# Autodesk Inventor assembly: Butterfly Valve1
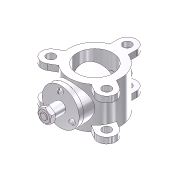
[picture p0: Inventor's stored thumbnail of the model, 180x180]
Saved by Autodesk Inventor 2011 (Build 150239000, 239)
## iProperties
Shininess: 64.0
Length Units: 11269
Angle Units: 11279
Time Units: 11290
Mass Units: 11283
Length Display Precision: 3
Angle Display Precision: 2
Created: 2002-02
Part Number: Butterfly Valve1
Document SubType Name: Assembly
Designer: ***
Density: 0.0
Volumn: 0.0
Area: 0.0
PropertySet Name: Model Information
Control State: 0
Master: False
Checked Out: False
Author: ***
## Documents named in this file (8)
- C:\Inventor_2011\c10_inv_2010_05042010\Butterfly Valve\Butterfly Valve.iam
- C:\Inventor_2011\c10_inv_2010_05042010\Butterfly Valve\Body.ipt
- C:\Inventor_2011\c10_inv_2010_05042010\Butterfly Valve\Shaft.ipt
- C:\Inventor_2011\c10_inv_2010_05042010\Butterfly Valve\Retainer.ipt
- C:\Inventor_2011\c10_inv_2010_05042010\Butterfly Valve\Screw.ipt
- C:\Inventor_2011\c10_inv_2010_05042010\Butterfly Valve\Arm.ipt
- C:\Inventor_2011\c10_inv_2010_05042010\Butterfly Valve\Plate.ipt
- C:\Inventor_2011\c10_inv_2010_05042010\Butterfly Valve\Nut.ipt
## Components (9 placed, 7 different names)
1. Body:1 — Insert:1, Angle:1, Insert:2, Insert:3, Angle:2
2. Shaft:1 — Insert:1, Angle:1, Insert:6, Insert:7, Insert:8
3. Retainer:1 — Insert:2, Insert:3, Insert:4, Insert:5
4. Arm:1 — Insert:5, Angle:2
5. Plate:1 — Insert:6, Insert:7
6. Nut:1 — Insert:8
7. Screw:1 — Insert:4
8. Screw:2
9. Screw:3
## Component patterns: Component Pattern 1 (3 elements)
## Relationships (10: Insert 8, Angle 2)
- Insert:1: Body:1 ↔ Shaft:1
- Angle:1: Body:1 ↔ Shaft:1
- Insert:2: Body:1 ↔ Retainer:1
- Insert:3: Body:1 ↔ Retainer:1
- Insert:4: Retainer:1 ↔ Screw:1
- Insert:5: Retainer:1 ↔ Arm:1
- Angle:2: Body:1 ↔ Arm:1
- Insert:6: Shaft:1 ↔ Plate:1
- Insert:7: Shaft:1 ↔ Plate:1
- Insert:8: Shaft:1 ↔ Nut:1
